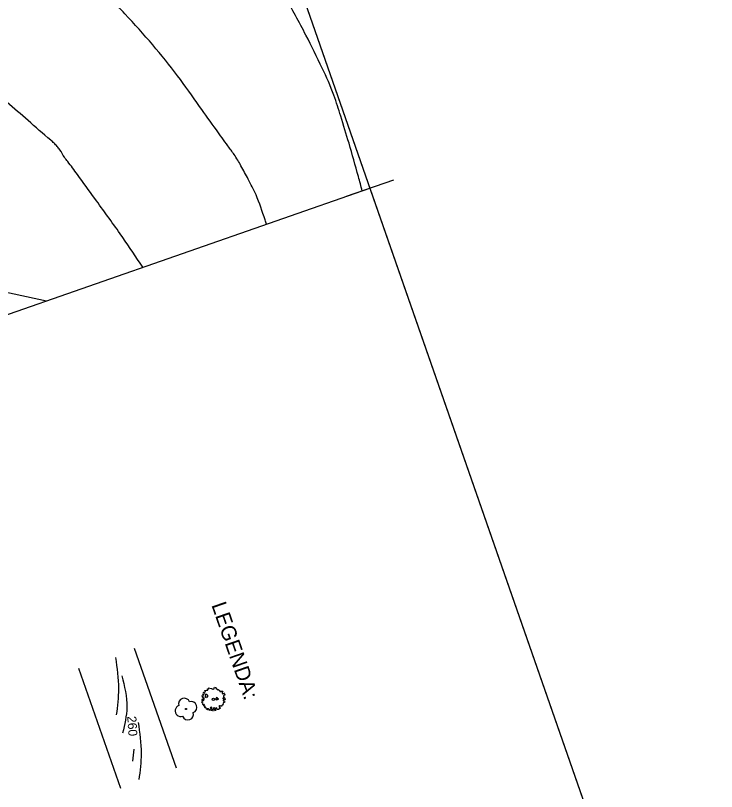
# Model space of a CAD drawing. Extents: x -477701 to -476785, y -1116511 to -1115314.
# Drawn here: x -476929.1 to -476789.2, y -1116232.6 to -1116077.7 of the extents above; entities that cross this region are included whole.
import ezdxf

# ---------------------------------------------------------------- set-up
doc = ezdxf.new("R2010")
doc.units = 0
for name, color, linetype in [('ramecek', 7, 'Continuous'), ('razitko', 7, 'Continuous'), ('SVK_STAT', 7, 'Continuous'), ('Vrstevnice_hlavni', 7, 'Continuous'), ('Vrstevnice_vedlejsi', 7, 'Continuous')]:
    doc.layers.add(name, color=color, linetype=linetype)

msp = doc.modelspace()

# ---------------------------------------------------------------- linework, layer by layer
at = {"layer": 'ramecek'}
msp.add_lwpolyline([(-476789.25, -1116310.52), (-477069.69, -1116408.3), (-477138.83, -1116210), (-476858.38, -1116112.23)], close=True, dxfattribs=at)
at = {"layer": 'razitko'}
for p, q in [((-476853.66, -1116110.58), (-476863.1, -1116113.87)), ((-476896.98, -1116228.01), (-476905.32, -1116204.09)), ((-476908.09, -1116232.04), (-476916.43, -1116208.12)), ((-476905.5, -1116224.19), (-476905.74, -1116226.59))]:
    msp.add_line(p, q, dxfattribs=at)
for points in [[(-477134.92, -1115319.05), (-476789.2, -1116310.67), (-477350.19, -1116506.26), (-477695.91, -1115514.64)], [(-477134.92, -1115319.05), (-476789.25, -1116310.52), (-477069.69, -1116408.3), (-477415.36, -1115416.83)], [(-476890.28, -1116216.48), (-476890.45, -1116216.42), (-476890.46, -1116216.29), (-476890.6, -1116216.16), (-476890.82, -1116216.14), (-476890.7, -1116216.27), (-476890.77, -1116216.32), (-476890.99, -1116216.2), (-476890.95, -1116216.2), (-476891.04, -1116215.93), (-476891.21, -1116215.97), (-476891.28, -1116215.86), (-476891.3, -1116215.75), (-476891.21, -1116215.69), (-476891.21, -1116215.62), (-476891.39, -1116215.53), (-476891.37, -1116215.65), (-476891.5, -1116215.55), (-476891.51, -1116215.41), (-476891.39, -1116215.32), (-476891.46, -1116215.25), (-476891.62, -1116215.35), (-476891.7, -1116215.28), (-476891.69, -1116215.14), (-476891.62, -1116215), (-476891.86, -1116214.95), (-476891.89, -1116214.84), (-476891.8, -1116214.67), (-476891.87, -1116214.54), (-476891.78, -1116214.48), (-476891.57, -1116214.5), (-476891.46, -1116214.41), (-476891.53, -1116214.28), (-476891.68, -1116214.24), (-476891.64, -1116214.32), (-476891.69, -1116214.37), (-476891.77, -1116214.42), (-476891.88, -1116214.3), (-476891.85, -1116214.2), (-476891.64, -1116214.16), (-476891.55, -1116214.18), (-476891.39, -1116214.09), (-476891.41, -1116214.09), (-476891.61, -1116213.91), (-476891.77, -1116213.94), (-476891.64, -1116213.77), (-476891.71, -1116213.67), (-476891.85, -1116213.66), (-476891.88, -1116213.57), (-476891.59, -1116213.46), (-476891.63, -1116213.31), (-476891.74, -1116213.27), (-476891.62, -1116213.13), (-476891.53, -1116213.2), (-476891.41, -1116213.13), (-476891.38, -1116212.99), (-476891.55, -1116212.9), (-476891.58, -1116212.82), (-476891.45, -1116212.8), (-476891.37, -1116212.82), (-476891.26, -1116212.77), (-476891.19, -1116212.67), (-476891.31, -1116212.55), (-476891.27, -1116212.47), (-476890.98, -1116212.4), (-476890.73, -1116212.44), (-476890.77, -1116212.18), (-476890.56, -1116212.16), (-476890.43, -1116212.1), (-476890.57, -1116211.97), (-476889.95, -1116212.06), (-476889.84, -1116212.19), (-476889.72, -1116212.15), (-476889.67, -1116212.21), (-476889.5, -1116212.16), (-476889.39, -1116212.09), (-476889.41, -1116211.94), (-476889.35, -1116211.85), (-476889.19, -1116211.87), (-476889.07, -1116212.12), (-476888.81, -1116212.24), (-476888.83, -1116212.36), (-476888.63, -1116212.24), (-476888.53, -1116212.46), (-476888.44, -1116212.45), (-476888.32, -1116212.64), (-476888.3, -1116212.68), (-476888.07, -1116212.67), (-476888.02, -1116212.61), (-476887.86, -1116212.62), (-476887.72, -1116212.65), (-476887.87, -1116212.91), (-476887.82, -1116213.07), (-476887.71, -1116213.18), (-476887.63, -1116213.11), (-476887.57, -1116212.96), (-476887.47, -1116213.17), (-476887.33, -1116213.37), (-476887.39, -1116213.48), (-476887.58, -1116213.5), (-476887.56, -1116213.62), (-476887.48, -1116213.75), (-476887.67, -1116213.95), (-476887.72, -1116214.09), (-476887.68, -1116214.17), (-476887.61, -1116214.07), (-476887.51, -1116214.03), (-476887.41, -1116213.91), (-476887.31, -1116214.05), (-476887.24, -1116214.29), (-476887.34, -1116214.37), (-476887.47, -1116214.29), (-476887.58, -1116214.29), (-476887.61, -1116214.51), (-476887.61, -1116214.55), (-476887.46, -1116214.5), (-476887.48, -1116214.63), (-476887.42, -1116214.68), (-476887.34, -1116214.78), (-476887.38, -1116214.91), (-476887.49, -1116214.9), (-476887.65, -1116214.97), (-476887.65, -1116215.11), (-476887.6, -1116215.18), (-476887.72, -1116215.31), (-476887.65, -1116215.38), (-476887.85, -1116215.41), (-476887.92, -1116215.49), (-476887.88, -1116215.58), (-476887.99, -1116215.66), (-476888.02, -1116215.6), (-476888.1, -1116215.64), (-476888.18, -1116215.64), (-476888.23, -1116215.62), (-476888.26, -1116215.56), (-476888.32, -1116215.52), (-476888.38, -1116215.5), (-476888.45, -1116215.55), (-476888.45, -1116215.65), (-476888.38, -1116215.85), (-476888.26, -1116215.98), (-476888.24, -1116216.08), (-476888.41, -1116216.11), (-476888.52, -1116216.19), (-476888.52, -1116216.27), (-476888.79, -1116216.3), (-476888.83, -1116216.25), (-476888.91, -1116216.18), (-476888.93, -1116215.98), (-476889.02, -1116216.01), (-476889.13, -1116216.14), (-476889.27, -1116216.02), (-476889.46, -1116215.98), (-476889.63, -1116216.08), (-476889.33, -1116216.2), (-476889.44, -1116216.26), (-476889.84, -1116216.21), (-476889.87, -1116216.36), (-476890, -1116216.51), (-476890.04, -1116216.5), (-476890.03, -1116216.39), (-476890.29, -1116216.27), (-476890.36, -1116216.34)], [(-476890.69, -1116213.75), (-476890.69, -1116213.42), (-476891.01, -1116213.28), (-476890.98, -1116213.22), (-476891.24, -1116213.31), (-476891.18, -1116213.51), (-476891.3, -1116213.78), (-476891.03, -1116213.89), (-476890.94, -1116213.69), (-476890.81, -1116213.75)], [(-476888.74, -1116214.18), (-476888.79, -1116214.05), (-476888.97, -1116213.91), (-476889.07, -1116214.04), (-476889.14, -1116214.24), (-476888.94, -1116214.44), (-476888.97, -1116214.27), (-476888.87, -1116214.25), (-476888.76, -1116214.29), (-476888.71, -1116214.3), (-476888.55, -1116214.22), (-476888.59, -1116214.14), (-476888.66, -1116214.09), (-476888.72, -1116214.14)], [(-476889.9, -1116216.05), (-476889.92, -1116215.9), (-476890.04, -1116215.79), (-476890.15, -1116215.88), (-476890.22, -1116216.01), (-476890.07, -1116216.1)], [(-476889.58, -1116216.5), (-476889.68, -1116216.45), (-476889.71, -1116216.5), (-476889.68, -1116216.52)], [(-476889.1, -1116216.36), (-476889.29, -1116216.32), (-476889.4, -1116216.34), (-476889.29, -1116216.45), (-476889.31, -1116216.49), (-476889.07, -1116216.44)]]:
    msp.add_lwpolyline(points, close=True, dxfattribs=at)
for centre, radius in [((-476889.6, -1116214.23), 0.238), ((-476895.05, -1116216.19), 0.112)]:
    msp.add_circle(centre, radius, dxfattribs=at)
for centre, start, end in [((-476895.42, -1116215.13), 19.2207, 199.2207), ((-476896.11, -1116216.56), 109.2207, 289.2207), ((-476893.99, -1116215.82), 289.2207, 109.2207), ((-476894.68, -1116217.25), 199.2207, 19.2207)]:
    msp.add_arc(centre, 1.12, start, end, dxfattribs=at)
for points in [[(-476909.12, -1116205.92), (-476908.53, -1116212.14), (-476908.97, -1116217.35)], [(-476907.86, -1116209.55), (-476906.87, -1116215.83), (-476907.7, -1116220.98)], [(-476904.61, -1116218.86), (-476904.02, -1116225.07), (-476904.46, -1116230.28)]]:
    msp.add_spline(points, degree=3, dxfattribs=at)
at = {"layer": 'SVK_STAT'}
msp.add_lwpolyline([(-477002.71, -1116118.59), (-477002.42, -1116118.67), (-476967.16, -1116126.19), (-476939.26, -1116131.2), (-476922.89, -1116134.72)], dxfattribs=at)
at = {"layer": 'Vrstevnice_hlavni'}
msp.add_spline([(-476879.02, -1116119.42), (-476879.29, -1116118.55), (-476881.09, -1116113.56), (-476882.64, -1116110.41), (-476884.09, -1116107.72), (-476885.45, -1116105.51), (-476886.7, -1116103.78), (-476889, -1116100.57), (-476892.34, -1116095.91), (-476896.73, -1116089.78), (-476901.69, -1116083.61), (-476907.24, -1116077.42), (-476913.37, -1116071.19), (-476917.84, -1116066.72), (-476920.65, -1116063.99), (-476921.79, -1116063.02), (-476922.89, -1116062.19), (-476923.94, -1116061.52), (-476925.96, -1116060.48)], degree=3, dxfattribs=at)
at = {"layer": 'Vrstevnice_vedlejsi'}
for points in [[(-476871.12, -1116081.67), (-476875.31, -1116073.87), (-476878.3, -1116068.41), (-476880.07, -1116065.29), (-476880.63, -1116064.51), (-476881.19, -1116063.8), (-476881.74, -1116063.16), (-476882.29, -1116062.6), (-476885.01, -1116060.5), (-476889.89, -1116056.86), (-476896.94, -1116051.69), (-476903.36, -1116047.14), (-476909.16, -1116043.21), (-476914.33, -1116039.91), (-476921.33, -1116036.09), (-476930.16, -1116031.75), (-476940.81, -1116026.9), (-476948.81, -1116023.46), (-476954.15, -1116021.45), (-476956.83, -1116020.86), (-476958.83, -1116020.44), (-476960.16, -1116020.2), (-476960.82, -1116020.13), (-476965.49, -1116019.91), (-476974.15, -1116019.52), (-476986.83, -1116018.98), (-476999.01, -1116018.3), (-477010.71, -1116017.5), (-477021.91, -1116016.57), (-477030.09, -1116015.74), (-477035.24, -1116015), (-477037.37, -1116014.35), (-477040.56, -1116013.08), (-477044.81, -1116011.18), (-477050.11, -1116008.65), (-477056.33, -1116006.12), (-477063.45, -1116003.59), (-477071.48, -1116001.06), (-477078.81, -1115999.52), (-477085.46, -1115998.98), (-477086.94, -1115999.04), (-477088.43, -1115999.2), (-477089.92, -1115999.37), (-477091.41, -1115999.43), (-477097.83, -1115998.92), (-477104.74, -1115997.44), (-477106.6, -1115996.87), (-477108.42, -1115996.21), (-477110.26, -1115995.56), (-477112.12, -1115994.99), (-477120, -1115993.69), (-477128.36, -1115993.52), (-477137.21, -1115994.5), (-477144.6, -1115995.69), (-477150.54, -1115997.09), (-477155.02, -1115998.69), (-477161.18, -1116002.18), (-477169.02, -1116007.55), (-477178.54, -1116014.8), (-477186.15, -1116020.75), (-477191.87, -1116025.41), (-477195.69, -1116028.76), (-477198.97, -1116032.74), (-477200.07, -1116034.35)], [(-476919.33, -1116106.05), (-476920.24, -1116104.55), (-476920.78, -1116103.86), (-476921.38, -1116103.22), (-476922.06, -1116102.63), (-476926.59, -1116098.7), (-476934.99, -1116091.42), (-476947.25, -1116080.8), (-476957.68, -1116072.81), (-476966.29, -1116067.47), (-476973.07, -1116064.75), (-476979.77, -1116062.46), (-476986.4, -1116060.58), (-476992.95, -1116059.11), (-477000.71, -1116057.57), (-477009.66, -1116055.93), (-477019.81, -1116054.21), (-477027.64, -1116052.95), (-477033.14, -1116052.13), (-477036.32, -1116051.77), (-477040.08, -1116051.08), (-477044.4, -1116050.05), (-477049.3, -1116048.7), (-477055.38, -1116047.74), (-477062.63, -1116047.17), (-477071.07, -1116046.98), (-477080.05, -1116047.47), (-477089.58, -1116048.62), (-477099.65, -1116050.44), (-477107.45, -1116051.76), (-477112.99, -1116052.58), (-477116.25, -1116052.91), (-477119.19, -1116053.33), (-477121.83, -1116053.85), (-477124.15, -1116054.46), (-477127.58, -1116055.64), (-477132.12, -1116057.4), (-477137.76, -1116059.72), (-477142.75, -1116062.09), (-477147.09, -1116064.52), (-477150.77, -1116067), (-477153.47, -1116068.86), (-477155.18, -1116070.1), (-477155.9, -1116070.71), (-477157.06, -1116072.06), (-477158.66, -1116074.13), (-477160.69, -1116076.93), (-477162.42, -1116079.37), (-477163.82, -1116081.43), (-477164.91, -1116083.12), (-477165.57, -1116084.44), (-477165.8, -1116085.38), (-477165.6, -1116085.95), (-477165.44, -1116086.46), (-477165.32, -1116086.91), (-477165.25, -1116087.31), (-477165.22, -1116087.63), (-477165.22, -1116087.85), (-477165.26, -1116087.99), (-477165.53, -1116088.09), (-477166.03, -1116088.15), (-477166.75, -1116088.16), (-477167.67, -1116088.25), (-477168.79, -1116088.4), (-477170.12, -1116088.63), (-477171.13, -1116088.88), (-477171.83, -1116089.16), (-477172.23, -1116089.45), (-477172.95, -1116089.69), (-477174.01, -1116089.87), (-477175.4, -1116089.99), (-477176.85, -1116090.02), (-477178.34, -1116089.96), (-477179.9, -1116089.82), (-477180.75, -1116089.75)], [(-476859.88, -1116112.75), (-476860.65, -1116109.9), (-476862.53, -1116103.26), (-476864.17, -1116097.85), (-476865.55, -1116093.66), (-476867.87, -1116088.26), (-476871.12, -1116081.67)], [(-476908.19, -1116121.3), (-476913.25, -1116114.29), (-476916.74, -1116109.49), (-476918.66, -1116106.88), (-476919.33, -1116106.05)], [(-476903.66, -1116128.01), (-476904.22, -1116127.16), (-476908.19, -1116121.3)]]:
    msp.add_spline(points, degree=3, dxfattribs=at)

# ---------------------------------------------------------------- texts
at = {"layer": 'razitko'}
for s, height, rotation, p in [('LEGENDA:', 3, 289.2207, (-476890.02, -1116195.41)), (' 260 ', 1.8, 273.6526, (-476906.83, -1116216.97))]:
    msp.add_text(s, height=height, rotation=rotation, dxfattribs=at).set_placement(p)

doc.saveas('drawing.dxf')
